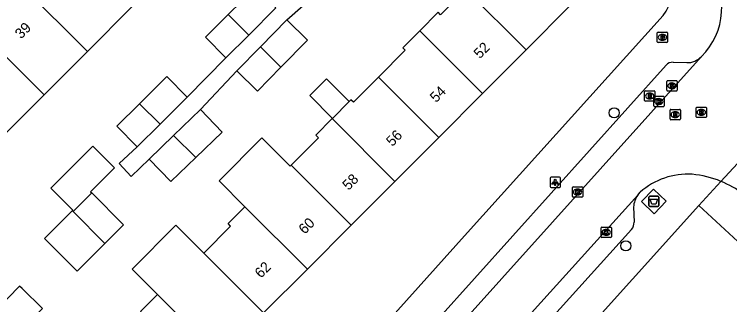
# Model space of a CAD drawing. Extents: x 159040 to 160094, y 381214 to 382518.
# Drawn here: x 159596.6 to 159665.8, y 381822.4 to 381850.5 of the extents above; entities that cross this region are included whole.
import ezdxf

# ---------------------------------------------------------------- set-up
doc = ezdxf.new("R2010")
doc.units = 0
for name, color, linetype in [('IMGEO_Afval_apart_plaats', 7, 'Continuous'), ('IMGEO_Boom', 7, 'Continuous'), ('IMGEO_Brandkraan', 7, 'Continuous'), ('IMGEO_Kolk', 7, 'Continuous'), ('IMGEO_Lichtpunt', 7, 'Continuous'), ('IMGEO_Pand', 7, 'Continuous'), ('IMGEO_Pand_nummerreeks', 7, 'Continuous'), ('IMGEO_Rijbaan_lokaal_open', 7, 'Continuous'), ('IMGEO_Rioolput', 7, 'Continuous'), ('IMGEO_Voetpad_gesloten', 7, 'Continuous'), ('IMGEO_Voetpad_open', 7, 'Continuous')]:
    doc.layers.add(name, color=color, linetype=linetype)

msp = doc.modelspace()

# ---------------------------------------------------------------- linework, layer by layer
at = {"layer": 'IMGEO_Afval_apart_plaats'}
for p, q in [((159657.988, 381831.984), (159657.988, 381832.784)), ((159657.988, 381832.784), (159657.988, 381831.984)), ((159658.088, 381832.884), (159658.878, 381832.884)), ((159658.878, 381832.884), (159658.088, 381832.884)), ((159658.978, 381832.784), (159658.978, 381831.984)), ((159658.978, 381831.984), (159658.978, 381832.784)), ((159658.878, 381831.884), (159658.088, 381831.884)), ((159658.088, 381831.884), (159658.878, 381831.884))]:
    msp.add_line(p, q, dxfattribs=at)
msp.add_lwpolyline([(159658.131, 381832.598), (159658.835, 381832.598), (159658.686, 381832.128), (159658.28, 381832.128), (159658.131, 381832.598)], dxfattribs=at)
for centre, start, end in [((159658.088, 381832.784), 90, 180), ((159658.088, 381832.784), 90, 180), ((159658.878, 381832.784), 0, 90), ((159658.878, 381832.784), 360, 90), ((159658.088, 381831.984), 180, 270), ((159658.088, 381831.984), 180, 270), ((159658.878, 381831.984), 270, 0), ((159658.878, 381831.984), 270, 0)]:
    msp.add_arc(centre, 0.1, start, end, dxfattribs=at)
at = {"layer": 'IMGEO_Boom'}
for centre in [(159654.653, 381840.933), (159655.781, 381828.086)]:
    msp.add_circle(centre, 0.489, dxfattribs=at)
at = {"layer": 'IMGEO_Brandkraan'}
for p, q in [((159658.819, 381847.805), (159658.819, 381848.657)), ((159658.894, 381848.731), (159659.746, 381848.731)), ((159659.307, 381848.511), (159659.332, 381848.511)), ((159659.82, 381848.657), (159659.82, 381847.805)), ((159659.746, 381847.731), (159658.894, 381847.731)), ((159659.33, 381847.951), (159659.305, 381847.951))]:
    msp.add_line(p, q, dxfattribs=at)
for points in [[(159658.819, 381847.805), (159658.819, 381848.657)], [(159658.894, 381848.731), (159659.746, 381848.731)], [(159659.167, 381848.431), (159659.167, 381848.031), (159659.38, 381848.031)], [(159659.398, 381848.431), (159659.167, 381848.431)], [(159659.82, 381848.657), (159659.82, 381847.805)], [(159659.746, 381847.731), (159658.894, 381847.731)], [(159659.346, 381848.35), (159659.292, 381848.35), (159659.292, 381848.274)], [(159659.292, 381848.274), (159659.345, 381848.274)], [(159659.354, 381848.198), (159659.292, 381848.198), (159659.292, 381848.117)], [(159659.292, 381848.117), (159659.354, 381848.117)]]:
    msp.add_lwpolyline(points, dxfattribs=at)
for centre, radius, start, end in [((159658.896, 381848.655), 0.0765, 91.55205, 178.44795), ((159658.896, 381848.655), 0.0765, 91.55205, 178.44795), ((159659.402, 381848.286), 0.145, 59.4692, 91.53667), ((159659.744, 381848.655), 0.0765, 1.55205, 88.44795), ((159659.744, 381848.655), 0.0765, 1.55205, 88.44795), ((159658.896, 381847.807), 0.0765, 181.55205, 268.44795), ((159658.896, 381847.807), 0.0765, 181.55205, 268.44795), ((159659.347, 381848.312), 0.0379, 267.82845, 90.93552), ((159659.355, 381848.157), 0.0404, 269.87594, 90.50774), ((159659.386, 381848.282), 0.251, 268.66757, 293.53466), ((159659.427, 381848.333), 0.0922, 285.51372, 58.15012), ((159659.432, 381848.141), 0.105, 301.31148, 78.98903), ((159659.744, 381847.807), 0.0765, 271.55205, 358.44795), ((159659.744, 381847.807), 0.0765, 271.55205, 358.44795)]:
    msp.add_arc(centre, radius, start, end, dxfattribs=at)
for centre, major_axis, ratio, start_param, end_param in [((159659.306, 381848.231), (-0.387, 0.002), 0.722429, 4.712389, 7.853982), ((159659.331, 381848.231), (-0.39, 0.002), 0.717154, 1.570796, 4.712389)]:
    msp.add_ellipse(centre, major_axis=major_axis, ratio=ratio, start_param=start_param, end_param=end_param, dxfattribs=at)
at = {"layer": 'IMGEO_Kolk'}
for p, q in [((159658.478, 381841.603), (159658.478, 381842.455)), ((159658.553, 381842.529), (159659.405, 381842.529)), ((159658.966, 381842.309), (159658.991, 381842.309)), ((159659.479, 381842.455), (159659.479, 381841.603)), ((159659.405, 381841.529), (159658.553, 381841.529)), ((159658.989, 381841.749), (159658.964, 381841.749)), ((159650.608, 381832.859), (159650.608, 381833.711)), ((159650.683, 381833.785), (159651.535, 381833.785)), ((159651.096, 381833.565), (159651.121, 381833.565)), ((159651.609, 381833.711), (159651.609, 381832.859)), ((159651.535, 381832.785), (159650.683, 381832.785)), ((159651.119, 381833.005), (159651.094, 381833.005)), ((159653.381, 381828.968), (159653.381, 381829.82)), ((159653.456, 381829.894), (159654.308, 381829.894)), ((159654.382, 381829.82), (159654.382, 381828.968)), ((159653.892, 381829.114), (159653.867, 381829.114)), ((159653.869, 381829.674), (159653.894, 381829.674)), ((159654.308, 381828.894), (159653.456, 381828.894))]:
    msp.add_line(p, q, dxfattribs=at)
for points in [[(159658.478, 381841.603), (159658.478, 381842.455)], [(159658.553, 381842.529), (159659.405, 381842.529)], [(159658.799, 381842.229), (159658.922, 381842.229), (159658.922, 381842.078), (159659.052, 381842.229), (159659.216, 381842.229), (159659.07, 381842.078), (159659.223, 381841.829), (159659.071, 381841.829), (159658.986, 381841.993), (159658.922, 381841.926), (159658.922, 381841.829), (159658.799, 381841.829), (159658.799, 381842.229)], [(159659.479, 381842.455), (159659.479, 381841.603)], [(159659.405, 381841.529), (159658.553, 381841.529)], [(159650.608, 381832.859), (159650.608, 381833.711)], [(159650.683, 381833.785), (159651.535, 381833.785)], [(159650.929, 381833.485), (159651.052, 381833.485), (159651.052, 381833.334), (159651.182, 381833.485), (159651.346, 381833.485), (159651.2, 381833.334), (159651.353, 381833.085), (159651.201, 381833.085), (159651.116, 381833.249), (159651.052, 381833.182), (159651.052, 381833.085), (159650.929, 381833.085), (159650.929, 381833.485)], [(159651.609, 381833.711), (159651.609, 381832.859)], [(159651.535, 381832.785), (159650.683, 381832.785)], [(159653.381, 381828.968), (159653.381, 381829.82)], [(159653.456, 381829.894), (159654.308, 381829.894)], [(159654.382, 381829.82), (159654.382, 381828.968)], [(159653.702, 381829.594), (159653.825, 381829.594), (159653.825, 381829.443), (159653.955, 381829.594), (159654.119, 381829.594), (159653.973, 381829.443), (159654.126, 381829.194), (159653.974, 381829.194), (159653.889, 381829.358), (159653.825, 381829.291), (159653.825, 381829.194), (159653.702, 381829.194), (159653.702, 381829.594)], [(159654.308, 381828.894), (159653.456, 381828.894)]]:
    msp.add_lwpolyline(points, dxfattribs=at)
for centre, start, end in [((159658.555, 381842.453), 91.55205, 178.44795), ((159658.555, 381842.453), 91.55205, 178.44795), ((159659.403, 381842.453), 1.55205, 88.44795), ((159659.403, 381842.453), 1.55205, 88.44795), ((159658.555, 381841.605), 181.55205, 268.44795), ((159658.555, 381841.605), 181.55205, 268.44795), ((159659.403, 381841.605), 271.55205, 358.44795), ((159659.403, 381841.605), 271.55205, 358.44795), ((159650.685, 381833.709), 91.55205, 178.44795), ((159650.685, 381833.709), 91.55205, 178.44795), ((159651.533, 381833.709), 1.55205, 88.44795), ((159651.533, 381833.709), 1.55205, 88.44795), ((159650.685, 381832.861), 181.55205, 268.44795), ((159650.685, 381832.861), 181.55205, 268.44795), ((159651.533, 381832.861), 271.55205, 358.44795), ((159651.533, 381832.861), 271.55205, 358.44795), ((159653.458, 381829.818), 91.55205, 178.44795), ((159653.458, 381829.818), 91.55205, 178.44795), ((159654.306, 381829.818), 1.55205, 88.44795), ((159654.306, 381829.818), 1.55205, 88.44795), ((159653.458, 381828.97), 181.55205, 268.44795), ((159653.458, 381828.97), 181.55205, 268.44795), ((159654.306, 381828.97), 271.55205, 358.44795), ((159654.306, 381828.97), 271.55205, 358.44795)]:
    msp.add_arc(centre, 0.0765, start, end, dxfattribs=at)
for centre, major_axis, ratio, start_param, end_param in [((159658.965, 381842.029), (-0.387, 0.002), 0.722429, 4.712389, 7.853982), ((159658.99, 381842.029), (-0.39, 0.002), 0.717154, 1.570796, 4.712389), ((159651.095, 381833.285), (-0.387, 0.002), 0.722429, 4.712389, 7.853982), ((159651.12, 381833.285), (-0.39, 0.002), 0.717154, 1.570796, 4.712389), ((159653.868, 381829.394), (-0.387, 0.002), 0.722429, 4.712389, 7.853982), ((159653.893, 381829.394), (-0.39, 0.002), 0.717154, 1.570796, 4.712389)]:
    msp.add_ellipse(centre, major_axis=major_axis, ratio=ratio, start_param=start_param, end_param=end_param, dxfattribs=at)
at = {"layer": 'IMGEO_Lichtpunt'}
for p, q in [((159648.448, 381834.634), (159648.448, 381833.827)), ((159648.448, 381834.634), (159648.448, 381833.827)), ((159649.35, 381834.729), (159648.542, 381834.729)), ((159649.35, 381834.729), (159648.542, 381834.729)), ((159649.444, 381833.827), (159649.444, 381834.634)), ((159649.444, 381833.827), (159649.444, 381834.634)), ((159648.542, 381833.733), (159649.35, 381833.733)), ((159648.542, 381833.733), (159649.35, 381833.733))]:
    msp.add_line(p, q, dxfattribs=at)
for points in [[(159648.822, 381834.298), (159648.861, 381834.27), (159648.673, 381834.008), (159648.635, 381834.035), (159648.822, 381834.298)], [(159648.924, 381834.25), (159648.971, 381834.25), (159648.971, 381833.928), (159648.924, 381833.928), (159648.924, 381834.25)], [(159649.034, 381834.27), (159649.072, 381834.297), (159649.259, 381834.035), (159649.22, 381834.007), (159649.034, 381834.27)]]:
    msp.add_lwpolyline(points, dxfattribs=at)
msp.add_circle((159648.947, 381834.432), 0.0994, dxfattribs=at)
for centre, start, end in [((159648.542, 381834.634), 90, 180), ((159648.542, 381834.634), 90, 180), ((159649.35, 381834.634), 0, 90), ((159649.35, 381834.634), 0, 90), ((159648.542, 381833.827), 180, 270), ((159648.542, 381833.827), 180, 270), ((159649.35, 381833.827), 270, 0), ((159649.35, 381833.827), 270, 360)]:
    msp.add_arc(centre, 0.0946, start, end, dxfattribs=at)
at = {"layer": 'IMGEO_Pand'}
for points in [[(159603.712, 381846.872), (159603.514, 381847.056), (159597.604, 381852.966)], [(159617.325, 381850.424), (159619.962, 381853.047), (159621.936, 381851.062)], [(159640.306, 381852.862), (159637.86, 381850.412), (159637.626, 381850.646), (159635.839, 381848.857)], [(159646.144, 381847.032), (159640.306, 381852.862)], [(159646.144, 381847.032), (159650.376, 381851.27)], [(159608.002, 381851.162), (159603.712, 381846.872)], [(159621.936, 381851.062), (159619.302, 381848.442)], [(159617.108, 381846.26), (159615.134, 381848.245), (159617.325, 381850.424)], [(159617.325, 381850.424), (159619.302, 381848.442)], [(159620.431, 381847.313), (159623.008, 381849.918)], [(159623.008, 381849.918), (159624.998, 381847.95), (159622.412, 381845.335)], [(159599.512, 381842.672), (159593.404, 381848.766)], [(159619.302, 381848.442), (159617.108, 381846.26)], [(159635.839, 381848.857), (159634.209, 381847.224), (159634.446, 381846.987), (159631.844, 381844.381)], [(159641.911, 381842.793), (159635.839, 381848.857)], [(159618.152, 381845.008), (159620.431, 381847.313)], [(159622.412, 381845.335), (159620.431, 381847.313)], [(159641.911, 381842.793), (159646.144, 381847.032)], [(159603.712, 381846.872), (159599.512, 381842.672)], [(159622.412, 381845.335), (159620.142, 381843.04), (159618.152, 381845.008)], [(159608.753, 381841.817), (159611.387, 381844.437), (159613.361, 381842.451)], [(159631.844, 381844.381), (159629.428, 381841.962), (159629.194, 381842.195), (159629.029, 381842.03)], [(159637.678, 381838.555), (159631.844, 381844.381)], [(159629.029, 381842.03), (159626.829, 381844.227), (159625.202, 381842.598), (159627.402, 381840.401)], [(159595.273, 381838.433), (159595.452, 381838.612), (159599.512, 381842.672)], [(159613.361, 381842.451), (159610.732, 381839.838)], [(159637.678, 381838.555), (159641.911, 381842.793)], [(159608.533, 381837.65), (159606.559, 381839.635), (159608.753, 381841.817)], [(159610.732, 381839.838), (159608.753, 381841.817)], [(159627.402, 381840.401), (159629.029, 381842.03)], [(159612.048, 381838.756), (159614.641, 381841.252)], [(159614.641, 381841.252), (159616.022, 381839.817), (159616.73, 381839.082), (159614.179, 381836.627)], [(159627.377, 381840.376), (159625.79, 381838.786), (159626.042, 381838.534), (159623.397, 381835.886)], [(159627.402, 381840.401), (159627.377, 381840.376)], [(159627.377, 381840.376), (159633.445, 381834.316)], [(159610.732, 381839.838), (159608.533, 381837.65)], [(159609.672, 381836.469), (159612.048, 381838.756)], [(159612.048, 381838.756), (159614.179, 381836.627)], [(159623.397, 381835.886), (159623.305, 381835.794), (159620.579, 381838.518), (159616.438, 381834.372), (159618.943, 381831.869)], [(159633.445, 381834.316), (159637.678, 381838.555)], [(159602.24, 381831.472), (159602.303, 381831.535), (159600.182, 381833.656), (159604.247, 381837.72), (159606.329, 381835.638), (159604.002, 381833.311), (159604.122, 381833.192)], [(159614.179, 381836.627), (159611.76, 381834.298), (159609.672, 381836.469)], [(159629.213, 381830.078), (159623.397, 381835.886)], [(159629.213, 381830.078), (159633.445, 381834.316)], [(159604.122, 381833.192), (159602.321, 381831.391)], [(159604.122, 381833.192), (159607.203, 381830.11), (159605.403, 381828.31)], [(159614.963, 381827.377), (159617.559, 381829.978), (159617.307, 381830.23), (159618.943, 381831.869)], [(159618.943, 381831.869), (159624.98, 381825.839)], [(159605.403, 381828.31), (159602.73, 381825.636), (159599.567, 381828.799), (159602.24, 381831.472)], [(159602.321, 381831.391), (159602.24, 381831.472)], [(159605.403, 381828.31), (159602.321, 381831.391)], [(159614.963, 381827.377), (159612.266, 381830.077), (159608.03, 381825.835), (159610.481, 381823.388)], [(159624.98, 381825.839), (159629.213, 381830.078)], [(159620.747, 381821.601), (159614.963, 381827.377)], [(159624.98, 381825.839), (159620.747, 381821.601)], [(159597.112, 381819.808), (159599.352, 381822.029), (159597.395, 381823.955), (159597.15, 381824.196), (159594.952, 381821.966)], [(159606.498, 381818.901), (159609.084, 381821.49), (159608.835, 381821.739), (159610.481, 381823.388)], [(159610.481, 381823.388), (159616.515, 381817.362)]]:
    msp.add_lwpolyline(points, dxfattribs=at)
at = {"layer": 'IMGEO_Rijbaan_lokaal_open'}
for points in [[(159663.088, 381846.379), (159638.897, 381819.482)], [(159664.979, 381834.318), (159668.563, 381838.196)], [(159656.948, 381832.988), (159657.168, 381833.258)], [(159642.102, 381816.592), (159656.948, 381832.988)]]:
    msp.add_lwpolyline(points, dxfattribs=at)
for centre, radius, start, end in [((159658.399, 381851.109), 6.661, 314.752, 37.24317), ((159661.768, 381828.122), 6.895, 86.47605, 131.85188), ((159661.23, 381825.09), 9.96, 67.88776, 84.45613), ((159661.052, 381824.769), 10.325, 53.65907, 67.64281)]:
    msp.add_arc(centre, radius, start, end, dxfattribs=at)
at = {"layer": 'IMGEO_Rioolput'}
for p, q in [((159659.74, 381843.117), (159659.74, 381843.969)), ((159659.815, 381844.043), (159660.667, 381844.043)), ((159660.228, 381843.823), (159660.253, 381843.823)), ((159660.741, 381843.969), (159660.741, 381843.117)), ((159657.59, 381842.131), (159657.59, 381842.983)), ((159657.665, 381843.057), (159658.517, 381843.057)), ((159658.591, 381842.983), (159658.591, 381842.131)), ((159660.667, 381843.043), (159659.815, 381843.043)), ((159660.251, 381843.263), (159660.226, 381843.263)), ((159658.101, 381842.277), (159658.076, 381842.277)), ((159658.078, 381842.837), (159658.103, 381842.837)), ((159658.517, 381842.057), (159657.665, 381842.057)), ((159660.054, 381840.341), (159660.054, 381841.193)), ((159660.129, 381841.267), (159660.981, 381841.267)), ((159660.542, 381841.047), (159660.567, 381841.047)), ((159661.055, 381841.193), (159661.055, 381840.341)), ((159662.576, 381840.56), (159662.576, 381841.412)), ((159662.651, 381841.486), (159663.503, 381841.486)), ((159663.064, 381841.266), (159663.089, 381841.266)), ((159663.577, 381841.412), (159663.577, 381840.56)), ((159660.981, 381840.267), (159660.129, 381840.267)), ((159660.565, 381840.487), (159660.54, 381840.487)), ((159663.503, 381840.486), (159662.651, 381840.486)), ((159663.087, 381840.706), (159663.062, 381840.706))]:
    msp.add_line(p, q, dxfattribs=at)
for points in [[(159659.74, 381843.117), (159659.74, 381843.969)], [(159659.815, 381844.043), (159660.667, 381844.043)], [(159660.329, 381843.741), (159660.077, 381843.743), (159660.077, 381843.343)], [(159660.255, 381843.662), (159660.201, 381843.662), (159660.201, 381843.581)], [(159660.201, 381843.581), (159660.253, 381843.581)], [(159660.741, 381843.969), (159660.741, 381843.117)], [(159657.59, 381842.131), (159657.59, 381842.983)], [(159657.665, 381843.057), (159658.517, 381843.057)], [(159658.591, 381842.983), (159658.591, 381842.131)], [(159660.667, 381843.043), (159659.815, 381843.043)], [(159660.077, 381843.343), (159660.201, 381843.343), (159660.201, 381843.505), (159660.212, 381843.505)], [(159660.259, 381843.476), (159660.33, 381843.343), (159660.47, 381843.343), (159660.405, 381843.469)], [(159658.179, 381842.755), (159657.927, 381842.757), (159657.927, 381842.357)], [(159657.927, 381842.357), (159658.051, 381842.357), (159658.051, 381842.519), (159658.062, 381842.519)], [(159658.105, 381842.676), (159658.051, 381842.676), (159658.051, 381842.595)], [(159658.051, 381842.595), (159658.103, 381842.595)], [(159658.109, 381842.49), (159658.18, 381842.357), (159658.32, 381842.357), (159658.255, 381842.483)], [(159658.517, 381842.057), (159657.665, 381842.057)], [(159660.054, 381840.341), (159660.054, 381841.193)], [(159660.129, 381841.267), (159660.981, 381841.267)], [(159660.643, 381840.965), (159660.391, 381840.967), (159660.391, 381840.567)], [(159660.569, 381840.886), (159660.515, 381840.886), (159660.515, 381840.805)], [(159660.515, 381840.805), (159660.567, 381840.805)], [(159661.055, 381841.193), (159661.055, 381840.341)], [(159662.576, 381840.56), (159662.576, 381841.412)], [(159662.651, 381841.486), (159663.503, 381841.486)], [(159663.165, 381841.184), (159662.913, 381841.186), (159662.913, 381840.786)], [(159662.913, 381840.786), (159663.037, 381840.786), (159663.037, 381840.948), (159663.048, 381840.948)], [(159663.091, 381841.105), (159663.037, 381841.105), (159663.037, 381841.024)], [(159663.037, 381841.024), (159663.089, 381841.024)], [(159663.095, 381840.919), (159663.166, 381840.786), (159663.306, 381840.786), (159663.241, 381840.912)], [(159663.577, 381841.412), (159663.577, 381840.56)], [(159660.981, 381840.267), (159660.129, 381840.267)], [(159660.391, 381840.567), (159660.515, 381840.567), (159660.515, 381840.729), (159660.526, 381840.729)], [(159660.573, 381840.7), (159660.644, 381840.567), (159660.784, 381840.567), (159660.719, 381840.693)], [(159663.503, 381840.486), (159662.651, 381840.486)]]:
    msp.add_lwpolyline(points, dxfattribs=at)
for centre, radius, start, end in [((159659.817, 381843.967), 0.0765, 91.55205, 178.44795), ((159659.817, 381843.967), 0.0765, 91.55205, 178.44795), ((159660.237, 381843.77), 0.19, 274.7715, 282.96867), ((159660.261, 381843.566), 0.0964, 77.00612, 93.18647), ((159660.275, 381843.623), 0.0378, 276.66336, 79.67722), ((159660.328, 381843.631), 0.109, 350.36119, 89.41601), ((159660.326, 381843.631), 0.112, 277.58423, 350.98172), ((159660.665, 381843.967), 0.0765, 1.55205, 88.44795), ((159660.665, 381843.967), 0.0765, 1.55205, 88.44795), ((159657.667, 381842.981), 0.0765, 91.55205, 178.44795), ((159657.667, 381842.981), 0.0765, 91.55205, 178.44795), ((159658.515, 381842.981), 0.0765, 1.55205, 88.44795), ((159658.515, 381842.981), 0.0765, 1.55205, 88.44795), ((159659.817, 381843.119), 0.0765, 181.55205, 268.44795), ((159659.817, 381843.119), 0.0765, 181.55205, 268.44795), ((159660.211, 381843.452), 0.0533, 26.02933, 88.69889), ((159660.31, 381843.416), 0.108, 29.51342, 73.79051), ((159660.665, 381843.119), 0.0765, 271.55205, 358.44795), ((159660.665, 381843.119), 0.0765, 271.55205, 358.44795), ((159658.061, 381842.466), 0.0533, 26.02933, 88.69889), ((159658.087, 381842.784), 0.19, 274.7715, 282.96867), ((159658.111, 381842.58), 0.0964, 77.00612, 93.18647), ((159658.125, 381842.637), 0.0378, 276.66336, 79.67722), ((159658.178, 381842.645), 0.109, 350.36119, 89.41601), ((159658.176, 381842.645), 0.112, 277.58423, 350.98172), ((159658.16, 381842.43), 0.108, 29.51342, 73.79051), ((159657.667, 381842.133), 0.0765, 181.55205, 268.44795), ((159657.667, 381842.133), 0.0765, 181.55205, 268.44795), ((159658.515, 381842.133), 0.0765, 271.55205, 358.44795), ((159658.515, 381842.133), 0.0765, 271.55205, 358.44795), ((159660.131, 381841.191), 0.0765, 91.55205, 178.44795), ((159660.131, 381841.191), 0.0765, 91.55205, 178.44795), ((159660.551, 381840.994), 0.19, 274.7715, 282.96867), ((159660.575, 381840.79), 0.0964, 77.00612, 93.18647), ((159660.589, 381840.847), 0.0378, 276.66336, 79.67722), ((159660.642, 381840.855), 0.109, 350.36119, 89.41601), ((159660.64, 381840.855), 0.112, 277.58423, 350.98172), ((159660.979, 381841.191), 0.0765, 1.55205, 88.44795), ((159660.979, 381841.191), 0.0765, 1.55205, 88.44795), ((159662.653, 381841.41), 0.0765, 91.55205, 178.44795), ((159662.653, 381841.41), 0.0765, 91.55205, 178.44795), ((159663.047, 381840.895), 0.0533, 26.02933, 88.69889), ((159663.073, 381841.213), 0.19, 274.7715, 282.96867), ((159663.097, 381841.009), 0.0964, 77.00612, 93.18647), ((159663.111, 381841.066), 0.0378, 276.66336, 79.67722), ((159663.164, 381841.074), 0.109, 350.36119, 89.41601), ((159663.162, 381841.074), 0.112, 277.58423, 350.98172), ((159663.146, 381840.859), 0.108, 29.51342, 73.79051), ((159663.501, 381841.41), 0.0765, 1.55205, 88.44795), ((159663.501, 381841.41), 0.0765, 1.55205, 88.44795), ((159660.131, 381840.343), 0.0765, 181.55205, 268.44795), ((159660.131, 381840.343), 0.0765, 181.55205, 268.44795), ((159660.525, 381840.676), 0.0533, 26.02933, 88.69889), ((159660.624, 381840.64), 0.108, 29.51342, 73.79051), ((159660.979, 381840.343), 0.0765, 271.55205, 358.44795), ((159660.979, 381840.343), 0.0765, 271.55205, 358.44795), ((159662.653, 381840.562), 0.0765, 181.55205, 268.44795), ((159662.653, 381840.562), 0.0765, 181.55205, 268.44795), ((159663.501, 381840.562), 0.0765, 271.55205, 358.44795), ((159663.501, 381840.562), 0.0765, 271.55205, 358.44795)]:
    msp.add_arc(centre, radius, start, end, dxfattribs=at)
for centre, major_axis, ratio, start_param, end_param in [((159660.227, 381843.543), (-0.387, 0.002), 0.722429, 4.712389, 7.853982), ((159660.252, 381843.543), (-0.39, 0.002), 0.717154, 1.570796, 4.712389), ((159658.077, 381842.557), (-0.387, 0.002), 0.722429, 4.712389, 7.853982), ((159658.102, 381842.557), (-0.39, 0.002), 0.717154, 1.570796, 4.712389), ((159660.541, 381840.767), (-0.387, 0.002), 0.722429, 4.712389, 7.853982), ((159660.566, 381840.767), (-0.39, 0.002), 0.717154, 1.570796, 4.712389), ((159663.063, 381840.986), (-0.387, 0.002), 0.722429, 4.712389, 7.853982), ((159663.088, 381840.986), (-0.39, 0.002), 0.717154, 1.570796, 4.712389)]:
    msp.add_ellipse(centre, major_axis=major_axis, ratio=ratio, start_param=start_param, end_param=end_param, dxfattribs=at)
at = {"layer": 'IMGEO_Voetpad_gesloten'}
msp.add_lwpolyline([(159657.293, 381832.356), (159658.441, 381833.574), (159659.674, 381832.412), (159658.526, 381831.194), (159657.293, 381832.356)], dxfattribs=at)
at = {"layer": 'IMGEO_Voetpad_open'}
for points in [[(159623.008, 381849.918), (159626.136, 381852.733), (159626.627, 381853.249)], [(159659.371, 381850.323), (159640.171, 381829.067), (159598.968, 381783.181)], [(159617.108, 381846.26), (159613.361, 381842.451)], [(159660.363, 381845.817), (159661.663, 381845.785)], [(159614.641, 381841.252), (159618.152, 381845.008)], [(159637.437, 381820.824), (159659.663, 381845.532)], [(159608.533, 381837.65), (159606.783, 381836.053), (159607.932, 381834.794), (159609.672, 381836.469)], [(159664.979, 381834.318), (159662.826, 381831.988)], [(159650.001, 381817.759), (159662.826, 381831.988)], [(159656.53, 381831.844), (159656.574, 381830.388)], [(159662.826, 381831.988), (159672.049, 381823.487)], [(159656.33, 381829.675), (159643.428, 381815.397)]]:
    msp.add_lwpolyline(points, dxfattribs=at)
for centre, radius, start, end in [((159657.204, 381852.242), 2.894, 318.47905, 40.00488), ((159661.744, 381847.598), 1.815, 267.45657, 317.80028), ((159660.284, 381845.009), 0.812, 84.41268, 139.89401), ((159658.451, 381831.79), 1.922, 141.45773, 178.39922), ((159655.577, 381830.331), 0.998, 318.93357, 3.2829)]:
    msp.add_arc(centre, radius, start, end, dxfattribs=at)

# ---------------------------------------------------------------- texts
at = {"layer": 'IMGEO_Pand_nummerreeks'}
for s, rotation, p in [('39', 45.00064, (159597.292, 381848.016)), ('52', 45.04012, (159641.655, 381846.104)), ('54', 45.04012, (159637.424, 381841.866)), ('56', 45.04021, (159633.19, 381837.626)), ('58', 45.04012, (159628.959, 381833.389)), ('60', 45.04021, (159624.725, 381829.149)), ('62', 45.04012, (159620.486, 381824.905))]:
    msp.add_text(s, height=1, rotation=rotation, dxfattribs=at).set_placement(p)

doc.saveas('drawing.dxf')
